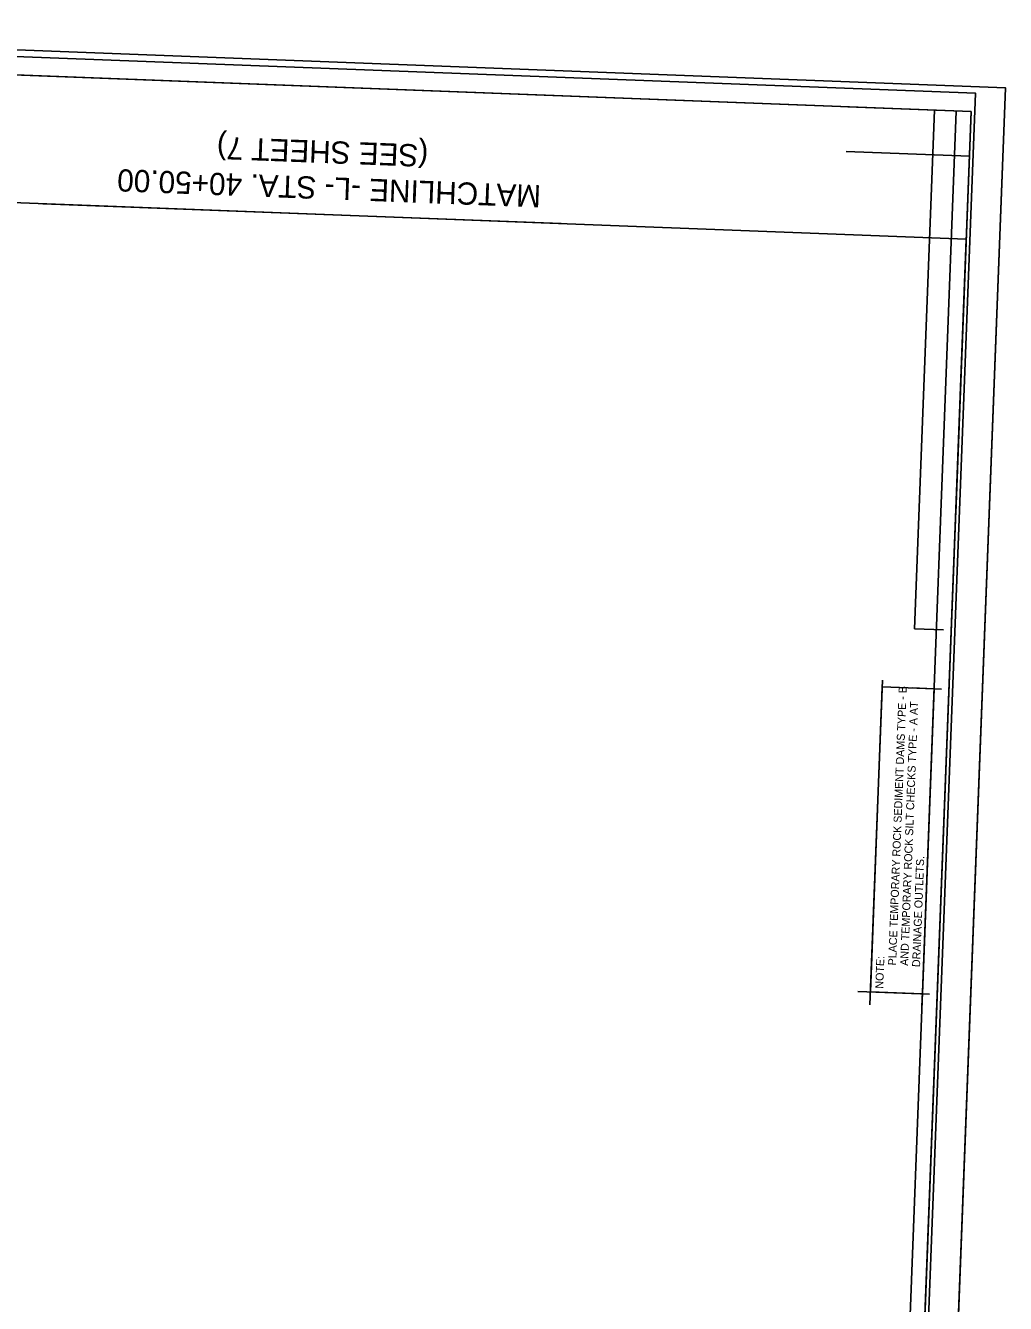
# Model space of a CAD drawing. Extents: x 2097083 to 2098242, y 681809 to 688195.
# Drawn here: x 2097581 to 2098242, y 687333 to 688195 of the extents above; entities that cross this region are included whole.
import ezdxf

# ---------------------------------------------------------------- set-up
doc = ezdxf.new("R2010")
doc.units = 0
for name, color, linetype in [('Construction Sheet Number Note CG CELL', 7, 'Continuous'), ('Matchline', 7, 'Continuous'), ('Matchline Text', 7, 'Continuous'), ('Scratch_Level_0', 7, 'Continuous'), ('Sheet Block Title CELL', 7, 'Continuous'), ('Sheet Data Field CELL', 7, 'Continuous'), ('Sheet Plan And Profile CELL', 7, 'Continuous'), ('Sheet Plot Border Inside CELL', 7, 'Continuous'), ('Sheet Sticker Exception Certification CELL', 7, 'Continuous')]:
    doc.layers.add(name, color=color, linetype=linetype)

msp = doc.modelspace()

# ---------------------------------------------------------------- linework, layer by layer
at = {"layer": 'Construction Sheet Number Note CG CELL'}
msp.add_lwpolyline([(2098150.9, 687542.81), (2098158.79, 687748.73), (2098193.86, 687747.39), (2098185.98, 687541.47)], close=True, dxfattribs=at)
at = {"layer": 'Matchline Text'}
msp.add_line((2097592.68, 688074.63), (2097942.42, 688061.22), dxfattribs=at)
at = {"layer": 'Scratch_Level_0'}
for p, q in [((2098218.82, 688136.72), (2098135.71, 688139.9)), ((2098153.95, 686706.26), (2098208.82, 688137.1)), ((2098163.94, 686705.88), (2098218.82, 688136.72)), ((2098194.1, 688137.66), (2098180.68, 687787.92)), ((2098208.43, 687865.92), (2098218.82, 688136.72)), ((2098217.67, 688106.74), (2098134.56, 688109.93)), ((2098180.68, 687787.92), (2098200.27, 687787.17)), ((2098150.56, 687534.04), (2098158.96, 687753.17)), ((2098179.15, 687747.95), (2098198.74, 687747.2)), ((2098185.64, 687532.69), (2098186.22, 687547.83)), ((2098142.32, 687543.14), (2098190.84, 687541.28))]:
    msp.add_line(p, q, dxfattribs=at)
at = {"layer": 'Sheet Block Title CELL'}
msp.add_lwpolyline([(2098177.45, 686470.58), (2098241.96, 688152.84), (2097147.77, 688194.8), (2097083.25, 686512.54)], close=True, dxfattribs=at)
at = {"layer": 'Sheet Data Field CELL'}
msp.add_lwpolyline([(2098157.96, 686484.33), (2098221.79, 688149.1), (2097167.58, 688189.54), (2097103.73, 686524.77)], close=True, dxfattribs=at)
at = {"layer": 'Sheet Plan And Profile CELL'}
msp.add_line((2098177.45, 686470.58), (2098241.96, 688152.84), dxfattribs=at)
at = {"layer": 'Sheet Plot Border Inside CELL'}
for points in [[(2098163.94, 686705.88), (2097114.34, 686736.39), (2097154.29, 687778.28), (2097155.66, 687814), (2097161.92, 687977.05), (2097398.05, 687968.01), (2097402.42, 688081.93), (2098215.52, 688050.75)], [(2098163.94, 686705.88), (2097114.34, 686736.39), (2097154.49, 687783.3), (2097155.83, 687818.24), (2097161.92, 687977.05), (2097398.05, 687968.01), (2097402.42, 688081.93), (2098215.52, 688050.75)]]:
    msp.add_lwpolyline(points, close=True, dxfattribs=at)
at = {"layer": 'Sheet Sticker Exception Certification CELL'}
for points in [[(2097169.59, 688176.98), (2097112.1, 686678.04), (2098161.33, 686637.81), (2098218.82, 688136.72)], [(2098161.33, 686637.81), (2097112.13, 686678.02), (2097161.91, 687977.05), (2097311.86, 687971.31), (2097319.54, 688171.2), (2098218.82, 688136.72)]]:
    msp.add_lwpolyline(points, close=True, dxfattribs=at)

# ---------------------------------------------------------------- texts
at = {"layer": 'Construction Sheet Number Note CG CELL'}
for s, p in [('PLACE TEMPORARY ROCK SEDIMENT DAMS TYPE - B', (2098168.21, 687560.66)), ('AND TEMPORARY ROCK SILT CHECKS TYPE - A AT', (2098176.31, 687560.38)), ('DRAINAGE OUTLETS.', (2098184.38, 687559.51)), ('NOTE:', (2098159.51, 687544.97))]:
    msp.add_text(s, height=5.4, rotation=87.80847, dxfattribs=at).set_placement(p)
at = {"layer": 'Matchline'}
for s, p in [('(SEE SHEET 7)', (2097852.91, 688114.35)), ('MATCHLINE -L- STA. 40+50.00', (2097928.97, 688087.04))]:
    msp.add_text(s, height=15, rotation=177.8037, dxfattribs=at).set_placement(p)

doc.saveas('drawing.dxf')
